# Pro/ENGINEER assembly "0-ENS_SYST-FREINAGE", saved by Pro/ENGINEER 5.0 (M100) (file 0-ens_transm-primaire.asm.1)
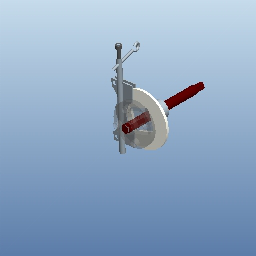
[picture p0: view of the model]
Units: millimeter Newton Second (mmNs); MM, TONNE, HOURS

Other parameters: ROTATION1_STATIC_FRICTION, ROTATION1_STATIC_FRICTION, ROTATION1_KINETIC_FRICTION, ROTATION1_KINETIC_FRICTION, ROTATION1_CONTACT_RADIUS, ROTATION1_CONTACT_RADIUS, ROTATION1_RESTITUTION, ROTATION1_RESTITUTION, ROTATION1_MINIMUM_LIMIT, ROTATION1_MINIMUM_LIMIT, ROTATION1_MAXIMUM_LIMIT, ROTATION1_MAXIMUM_LIMIT, ROTATION1_ZERO_POSITION, ROTATION1_ZERO_POSITION

Other components: 01_BATI-FREINAGE, E-ARBRE_ENTREE, E-ARBRE_SORTIE, E-AXE_FREIN

Other named items: A-DROITE, A-DESSUS, A-FACE, A-R0, ACS0, ACS1, S1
